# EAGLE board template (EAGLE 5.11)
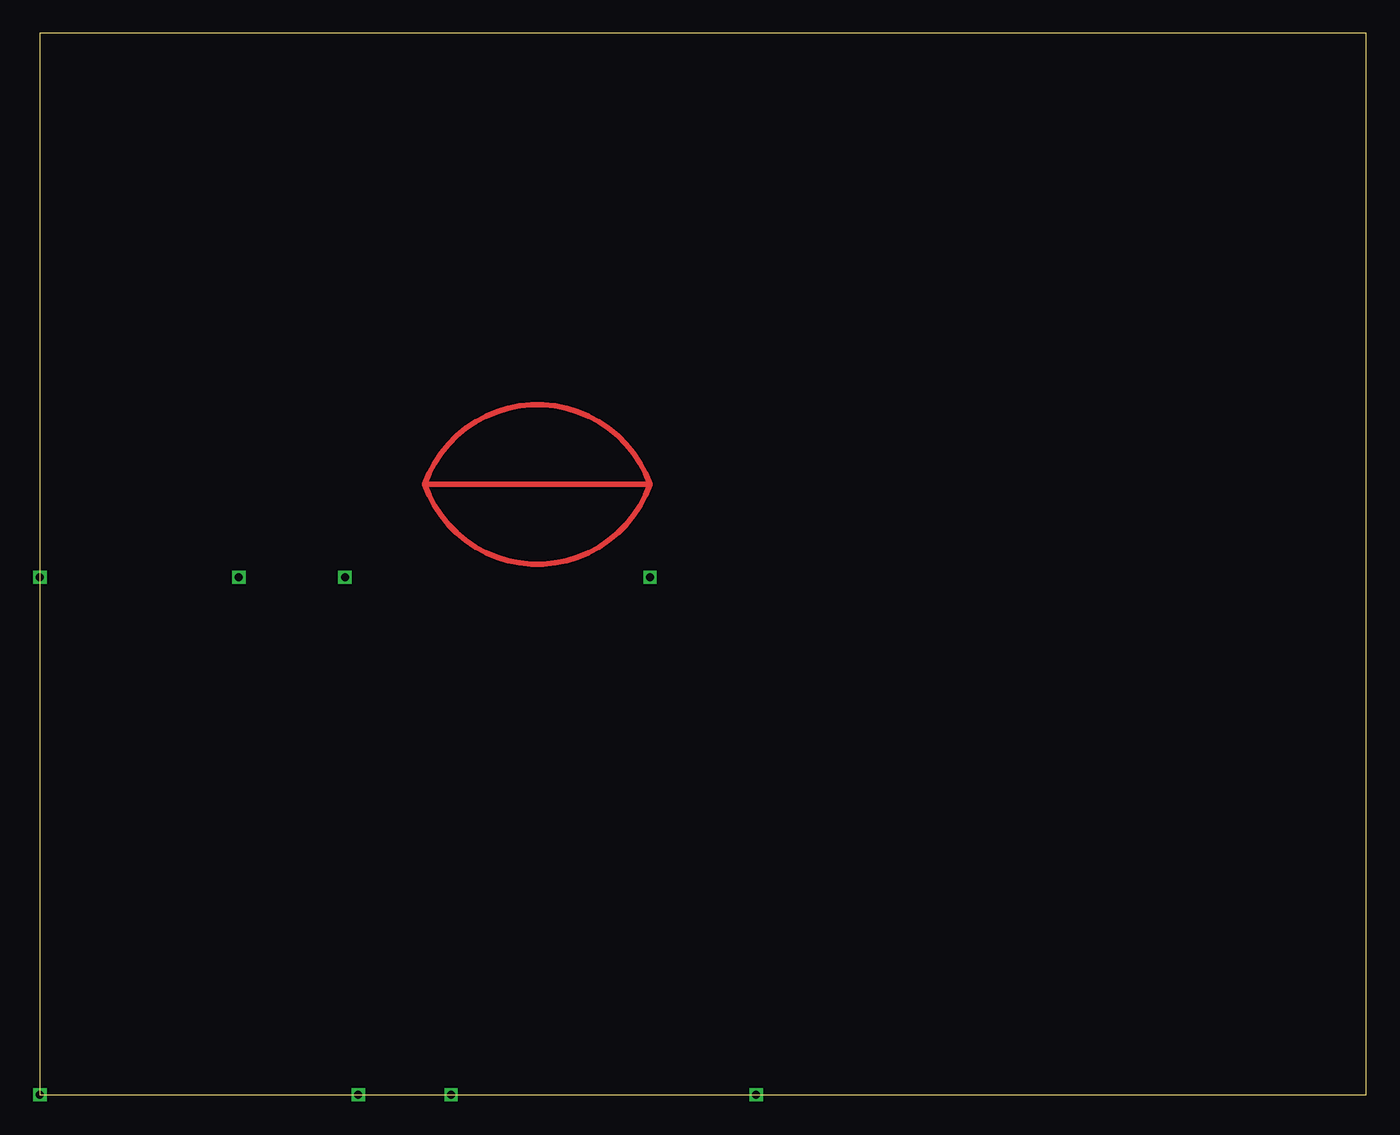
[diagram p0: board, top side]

Size 100 x 80 mm. Coordinates in mm from the lower left corner, seen from the top.
Outline: 0,0 100,0 100,80 0,80 0,0
Copper layers (1*16): Top 0.035mm / dielectric 1.5mm / Bottom 0.035mm
Design rules "default": minimum track width 10mil, minimum drill 0.6mm, track to track 8mil, track to pad 8mil, pad to pad 8mil, via to via 8mil, smd to smd 8mil, copper to edge 40mil, drill to drill 8mil, minimum pad ring 10mil, minimum via ring 8mil, stop-mask expansion 4mil, vias tented up to drill 0mil, thermal gap 10mil

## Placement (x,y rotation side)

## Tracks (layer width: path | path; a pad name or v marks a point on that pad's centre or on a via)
N$1  (via drill 0.6)
  other vias: 0,0
N$2  (via drill 0.6)
  other vias: 24,0
N$3  (via drill 0.6)
  other vias: 31,0
N$4  (via drill 0.6)
  other vias: 54,0
N$5  (via drill 0.6)
  other vias: 0,39
N$6  (via drill 0.6)
  other vias: 46,39
N$7  (via drill 0.6)
  other vias: 23,39
N$8  (via drill 0.6)
  other vias: 15,39
N$11
  Top 0.406: 46,46 arc-141 29,46 | 29,46 arc-141 46,46 | 29,46 46,46

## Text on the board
Document: 1mm=1ft | burbank | tartarian | yel del | red haven | plum | cherry | 15 | peach | 12 | 12 | 15 | stella | santa rosa | staymans | cherry | plum | winesap | 12 | honey | 8 | 12 | veteran | crisp | 6 | peach | 10 | raspberry | bartlett | pear | 15 | seckel | pear | 15 | white | white | peach | peach | 10 | 10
